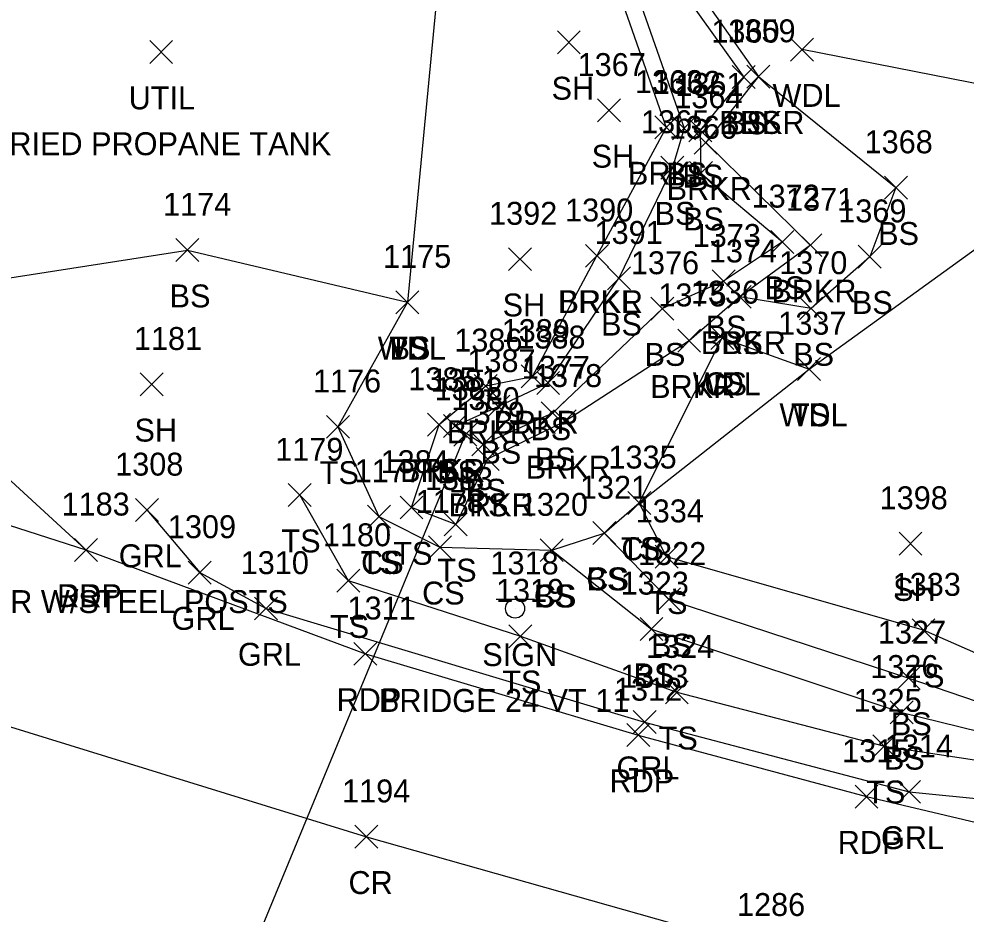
# Model space of a CAD drawing. Extents: x 1547013 to 1549434, y 267998 to 268739.
# Drawn here: x 1548542.6 to 1548625.3, y 268107.9 to 268186.1 of the extents above; entities that cross this region are included whole.
import ezdxf

# ---------------------------------------------------------------- set-up
doc = ezdxf.new("R2010")
doc.units = 0
for name, color, linetype in [('D_A', 7, 'Continuous'), ('D_I', 7, 'Continuous'), ('D_TIC', 7, 'Continuous'), ('DCP', 7, 'Continuous'), ('L_A', 7, 'Continuous'), ('L_I', 7, 'Continuous'), ('L_TIC', 7, 'Continuous'), ('LAWA', 7, 'Continuous'), ('LAWE', 7, 'Continuous'), ('LELB', 7, 'Continuous'), ('P_A', 7, 'Continuous'), ('P_I', 7, 'Continuous'), ('P_TIC', 7, 'Continuous'), ('PET', 7, 'Continuous'), ('PRC', 7, 'Continuous'), ('R_A', 7, 'Continuous'), ('R_C', 7, 'Continuous'), ('R_I', 7, 'Continuous'), ('R_TIC', 7, 'Continuous'), ('RDP', 7, 'Continuous'), ('RGR', 7, 'Continuous'), ('S_A', 7, 'Continuous'), ('S_C', 7, 'Continuous'), ('S_I', 7, 'Continuous'), ('SSGN', 7, 'Continuous'), ('U_A', 7, 'Continuous'), ('U_C', 7, 'Continuous'), ('UDEFAULT', 7, 'Continuous')]:
    doc.layers.add(name, color=color, linetype=linetype)

msp = doc.modelspace()

# ---------------------------------------------------------------- linework, layer by layer
at = {"layer": 'D_TIC'}
for points in [[(1548580.569, 268148.791), (1548582.569, 268150.791)], [(1548582.569, 268148.791), (1548580.569, 268150.791)]]:
    msp.add_lwpolyline(points, dxfattribs=at)
at = {"layer": 'DCP'}
msp.add_lwpolyline([(1548553.082, 268080.82), (1548581.569, 268149.791)], dxfattribs=at)
at = {"layer": 'L_TIC'}
for points in [[(1548589.597, 268183.027), (1548591.597, 268185.027)], [(1548591.597, 268183.027), (1548589.597, 268185.027)], [(1548609.953, 268182.401), (1548611.953, 268184.401)], [(1548611.953, 268182.401), (1548609.953, 268184.401)], [(1548604.859, 268180.006), (1548606.859, 268182.006)], [(1548606.859, 268180.006), (1548604.859, 268182.006)], [(1548606.135, 268180.039), (1548608.135, 268182.039)], [(1548608.135, 268180.039), (1548606.135, 268182.039)], [(1548606.135, 268180.039), (1548608.135, 268182.039)], [(1548608.135, 268180.039), (1548606.135, 268182.039)], [(1548593.098, 268177.092), (1548595.098, 268179.092)], [(1548595.098, 268177.092), (1548593.098, 268179.092)], [(1548598.102, 268175.604), (1548600.102, 268177.604)], [(1548600.102, 268175.604), (1548598.102, 268177.604)], [(1548599.647, 268175.537), (1548601.647, 268177.537)], [(1548601.647, 268175.537), (1548599.647, 268177.537)], [(1548601.065, 268175.361), (1548603.065, 268177.361)], [(1548603.065, 268175.361), (1548601.065, 268177.361)], [(1548601.54, 268174.278), (1548603.54, 268176.278)], [(1548603.54, 268174.278), (1548601.54, 268176.278)], [(1548598.633, 268172.103), (1548600.633, 268174.103)], [(1548600.633, 268172.103), (1548598.633, 268174.103)], [(1548601.121, 268171.618), (1548603.121, 268173.618)], [(1548603.121, 268171.618), (1548601.121, 268173.618)], [(1548618.144, 268170.348), (1548620.144, 268172.348)], [(1548620.144, 268170.348), (1548618.144, 268172.348)], [(1548608.234, 268165.605), (1548610.234, 268167.605)], [(1548610.234, 268165.605), (1548608.234, 268167.605)], [(1548556.31, 268164.896), (1548558.31, 268166.896)], [(1548558.31, 268164.896), (1548556.31, 268166.896)], [(1548610.675, 268165.326), (1548612.675, 268167.326)], [(1548612.675, 268165.326), (1548610.675, 268167.326)], [(1548585.328, 268164.108), (1548587.328, 268166.108)], [(1548587.328, 268164.108), (1548585.328, 268166.108)], [(1548592.044, 268164.396), (1548594.044, 268166.396)], [(1548594.044, 268164.396), (1548592.044, 268166.396)], [(1548592.044, 268164.396), (1548594.044, 268166.396)], [(1548594.044, 268164.396), (1548592.044, 268166.396)], [(1548615.854, 268164.32), (1548617.854, 268166.32)], [(1548617.854, 268164.32), (1548615.854, 268166.32)], [(1548593.964, 268162.437), (1548595.964, 268164.437)], [(1548595.964, 268162.437), (1548593.964, 268164.437)], [(1548593.964, 268162.437), (1548595.964, 268164.437)], [(1548595.964, 268162.437), (1548593.964, 268164.437)], [(1548603.096, 268162.172), (1548605.096, 268164.172)], [(1548605.096, 268162.172), (1548603.096, 268164.172)], [(1548604.509, 268160.821), (1548606.509, 268162.821)], [(1548606.509, 268160.821), (1548604.509, 268162.821)], [(1548604.509, 268160.821), (1548606.509, 268162.821)], [(1548606.509, 268160.821), (1548604.509, 268162.821)], [(1548575.504, 268160.346), (1548577.504, 268162.346)], [(1548577.504, 268160.346), (1548575.504, 268162.346)], [(1548575.504, 268160.346), (1548577.504, 268162.346)], [(1548577.504, 268160.346), (1548575.504, 268162.346)], [(1548575.504, 268160.346), (1548577.504, 268162.346)], [(1548577.504, 268160.346), (1548575.504, 268162.346)], [(1548597.76, 268159.793), (1548599.76, 268161.793)], [(1548599.76, 268159.793), (1548597.76, 268161.793)], [(1548610.73, 268159.799), (1548612.73, 268161.799)], [(1548612.73, 268159.799), (1548610.73, 268161.799)], [(1548600.099, 268156.985), (1548602.099, 268158.985)], [(1548602.099, 268156.985), (1548600.099, 268158.985)], [(1548602.989, 268157.225), (1548604.989, 268159.225)], [(1548604.989, 268157.225), (1548602.989, 268159.225)], [(1548602.989, 268157.225), (1548604.989, 268159.225)], [(1548604.989, 268157.225), (1548602.989, 268159.225)], [(1548610.56, 268154.512), (1548612.56, 268156.512)], [(1548612.56, 268154.512), (1548610.56, 268156.512)], [(1548610.56, 268154.512), (1548612.56, 268156.512)], [(1548612.56, 268154.512), (1548610.56, 268156.512)], [(1548586.429, 268153.87), (1548588.429, 268155.87)], [(1548588.429, 268153.87), (1548586.429, 268155.87)], [(1548587.793, 268153.304), (1548589.793, 268155.304)], [(1548589.793, 268153.304), (1548587.793, 268155.304)], [(1548553.197, 268153.181), (1548555.197, 268155.181)], [(1548555.197, 268153.181), (1548553.197, 268155.181)], [(1548582.343, 268153.042), (1548584.343, 268155.042)], [(1548584.343, 268153.042), (1548582.343, 268155.042)], [(1548583.434, 268151.245), (1548585.434, 268153.245)], [(1548585.434, 268151.245), (1548583.434, 268153.245)], [(1548588.179, 268150.662), (1548590.179, 268152.662)], [(1548590.179, 268150.662), (1548588.179, 268152.662)], [(1548589.244, 268149.946), (1548591.244, 268151.946)], [(1548591.244, 268149.946), (1548589.244, 268151.946)], [(1548569.443, 268149.472), (1548571.443, 268151.472)], [(1548571.443, 268149.472), (1548569.443, 268151.472)], [(1548578.272, 268149.661), (1548580.272, 268151.661)], [(1548580.272, 268149.661), (1548578.272, 268151.661)], [(1548578.272, 268149.661), (1548580.272, 268151.661)], [(1548580.272, 268149.661), (1548578.272, 268151.661)], [(1548579.655, 268149.536), (1548581.655, 268151.536)], [(1548581.655, 268149.536), (1548579.655, 268151.536)], [(1548582.124, 268147.933), (1548584.124, 268149.933)], [(1548584.124, 268147.933), (1548582.124, 268149.933)], [(1548582.506, 268146.655), (1548584.506, 268148.655)], [(1548584.506, 268146.655), (1548582.506, 268148.655)], [(1548582.506, 268146.655), (1548584.506, 268148.655)], [(1548584.506, 268146.655), (1548582.506, 268148.655)], [(1548566.105, 268143.51), (1548568.105, 268145.51)], [(1548568.105, 268143.51), (1548566.105, 268145.51)], [(1548595.744, 268142.829), (1548597.744, 268144.829)], [(1548597.744, 268142.829), (1548595.744, 268144.829)], [(1548595.744, 268142.829), (1548597.744, 268144.829)], [(1548597.744, 268142.829), (1548595.744, 268144.829)], [(1548573.025, 268141.632), (1548575.025, 268143.632)], [(1548575.025, 268141.632), (1548573.025, 268143.632)], [(1548573.025, 268141.632), (1548575.025, 268143.632)], [(1548575.025, 268141.632), (1548573.025, 268143.632)], [(1548575.861, 268142.428), (1548577.861, 268144.428)], [(1548577.861, 268142.428), (1548575.861, 268144.428)], [(1548579.72, 268140.956), (1548581.72, 268142.956)], [(1548581.72, 268140.956), (1548579.72, 268142.956)], [(1548592.686, 268140.194), (1548594.686, 268142.194)], [(1548594.686, 268140.194), (1548592.686, 268142.194)], [(1548592.686, 268140.194), (1548594.686, 268142.194)], [(1548594.686, 268140.194), (1548592.686, 268142.194)], [(1548619.408, 268139.276), (1548621.408, 268141.276)], [(1548621.408, 268139.276), (1548619.408, 268141.276)], [(1548578.349, 268138.961), (1548580.349, 268140.961)], [(1548580.349, 268138.961), (1548578.349, 268140.961)], [(1548588.098, 268138.705), (1548590.098, 268140.705)], [(1548590.098, 268138.705), (1548588.098, 268140.705)], [(1548588.098, 268138.705), (1548590.098, 268140.705)], [(1548590.098, 268138.705), (1548588.098, 268140.705)], [(1548598.121, 268138.132), (1548600.121, 268140.132)], [(1548600.121, 268138.132), (1548598.121, 268140.132)], [(1548570.343, 268136.045), (1548572.343, 268138.045)], [(1548572.343, 268136.045), (1548570.343, 268138.045)], [(1548598.329, 268134.41), (1548600.329, 268136.41)], [(1548600.329, 268134.41), (1548598.329, 268136.41)], [(1548596.809, 268131.823), (1548598.809, 268133.823)], [(1548598.809, 268131.823), (1548596.809, 268133.823)], [(1548620.549, 268131.719), (1548622.549, 268133.719)], [(1548622.549, 268131.719), (1548620.549, 268133.719)], [(1548585.37, 268131.193), (1548587.37, 268133.193)], [(1548587.37, 268131.193), (1548585.37, 268133.193)], [(1548619.257, 268127.544), (1548621.257, 268129.544)], [(1548621.257, 268127.544), (1548619.257, 268129.544)], [(1548599.022, 268126.304), (1548601.022, 268128.304)], [(1548601.022, 268126.304), (1548599.022, 268128.304)], [(1548618.648, 268124.545), (1548620.648, 268126.545)], [(1548620.648, 268124.545), (1548618.648, 268126.545)], [(1548617.136, 268121.596), (1548619.136, 268123.596)], [(1548619.136, 268121.596), (1548617.136, 268123.596)]]:
    msp.add_lwpolyline(points, dxfattribs=at)
at = {"layer": 'LAWA'}
for points in [[(1548576.365, 268223.8), (1548575.522, 268199.76), (1548579.378, 268191.112), (1548576.504, 268161.346)], [(1548603.989, 268158.225), (1548611.56, 268155.512), (1548628.675, 268167.856), (1548635.403, 268178.61), (1548610.953, 268183.401)]]:
    msp.add_lwpolyline(points, dxfattribs=at)
at = {"layer": 'LAWE'}
for points in [[(1548595.415, 268212.858), (1548593.341, 268193.065), (1548599.102, 268176.604), (1548593.044, 268165.396)], [(1548604.607, 268199.688), (1548599.756, 268191.551), (1548607.135, 268181.039), (1548602.54, 268175.278), (1548611.675, 268166.326), (1548605.509, 268161.821), (1548601.099, 268157.985), (1548590.244, 268150.946), (1548583.506, 268147.655)], [(1548579.272, 268150.661), (1548583.343, 268154.042), (1548587.429, 268154.87), (1548593.044, 268165.396)]]:
    msp.add_lwpolyline(points, dxfattribs=at)
at = {"layer": 'LELB'}
for points in [[(1548597.062, 268212.241), (1548594.748, 268193.422), (1548600.647, 268176.537), (1548599.633, 268173.103), (1548594.964, 268163.437)], [(1548641.103, 268197.228), (1548618.586, 268200.881), (1548604.348, 268203.165), (1548598.059, 268191.896), (1548605.859, 268181.006), (1548602.065, 268176.361), (1548602.121, 268172.618), (1548609.234, 268166.605), (1548604.096, 268163.172), (1548598.76, 268160.793), (1548589.179, 268151.662), (1548583.124, 268148.933), (1548580.655, 268150.536), (1548584.434, 268152.245), (1548588.793, 268154.304), (1548594.964, 268163.437)], [(1548607.135, 268181.039), (1548619.144, 268171.348), (1548616.854, 268165.32), (1548611.73, 268160.799), (1548605.509, 268161.821)], [(1548513.425, 268171.188), (1548524.997, 268163.116), (1548533.554, 268162.21), (1548557.31, 268165.896), (1548576.504, 268161.346)], [(1548576.504, 268161.346), (1548570.443, 268150.472), (1548574.025, 268142.632)], [(1548574.025, 268142.632), (1548579.349, 268139.961), (1548589.098, 268139.705), (1548593.686, 268141.194), (1548596.744, 268143.829), (1548603.989, 268158.225)], [(1548567.105, 268144.51), (1548571.343, 268137.045), (1548586.37, 268132.193), (1548600.022, 268127.304), (1548618.136, 268122.596), (1548638.08, 268119.574), (1548638.109, 268125.451), (1548621.549, 268132.719), (1548599.121, 268139.132), (1548596.744, 268143.829), (1548611.56, 268155.512)], [(1548583.506, 268147.655), (1548580.72, 268141.956), (1548576.861, 268143.428), (1548579.272, 268150.661)], [(1548593.686, 268141.194), (1548599.329, 268135.41), (1548620.257, 268128.544), (1548636.788, 268122.874), (1548636.589, 268121.375)], [(1548589.098, 268139.705), (1548597.809, 268132.823), (1548619.648, 268125.545), (1548636.589, 268121.375)]]:
    msp.add_lwpolyline(points, dxfattribs=at)
at = {"layer": 'P_TIC'}
for points in [[(1548547.446, 268138.726), (1548549.446, 268140.726)], [(1548549.446, 268138.726), (1548547.446, 268140.726)], [(1548571.84, 268129.652), (1548573.84, 268131.652)], [(1548573.84, 268129.652), (1548571.84, 268131.652)], [(1548595.653, 268122.565), (1548597.653, 268124.565)], [(1548597.653, 268122.565), (1548595.653, 268124.565)], [(1548615.573, 268117.195), (1548617.573, 268119.195)], [(1548617.573, 268117.195), (1548615.573, 268119.195)], [(1548571.932, 268113.689), (1548573.932, 268115.689)], [(1548573.932, 268113.689), (1548571.932, 268115.689)]]:
    msp.add_lwpolyline(points, dxfattribs=at)
at = {"layer": 'PET'}
msp.add_lwpolyline([(1548291.291, 268251.793), (1548331.751, 268232.06), (1548365.572, 268215.99), (1548397.036, 268199.918), (1548430.532, 268185.01), (1548469.559, 268167.88), (1548505.567, 268153.53), (1548548.446, 268139.726), (1548572.84, 268130.652), (1548596.653, 268123.565), (1548616.573, 268118.195), (1548655.338, 268109.044), (1548680.933, 268103.123), (1548700.801, 268099.763), (1548753.548, 268092.312), (1548788.113, 268088.532), (1548842.075, 268084.262), (1548868.979, 268083.237)], dxfattribs=at)
at = {"layer": 'PRC'}
msp.add_lwpolyline([(1548285.227, 268237.15), (1548330.43, 268214.749), (1548376.37, 268192.576), (1548426.535, 268169.593), (1548464.29, 268153.498), (1548497.35, 268140.085), (1548534.695, 268126.495), (1548572.932, 268114.689), (1548608.018, 268104.772), (1548637.809, 268097.375), (1548663.07, 268091.687), (1548686.377, 268086.96), (1548723.692, 268081.048), (1548751.899, 268076.9), (1548786.742, 268073.357), (1548818.759, 268070.537), (1548866.796, 268068.078)], dxfattribs=at)
at = {"layer": 'R_TIC'}
for points in [[(1548552.774, 268142.213), (1548554.774, 268144.213)], [(1548554.774, 268142.213), (1548552.774, 268144.213)], [(1548547.446, 268138.726), (1548549.446, 268140.726)], [(1548549.446, 268138.726), (1548547.446, 268140.726)], [(1548557.382, 268136.75), (1548559.382, 268138.75)], [(1548559.382, 268136.75), (1548557.382, 268138.75)], [(1548563.172, 268133.614), (1548565.172, 268135.614)], [(1548565.172, 268133.614), (1548563.172, 268135.614)], [(1548596.208, 268123.696), (1548598.208, 268125.696)], [(1548598.208, 268123.696), (1548596.208, 268125.696)], [(1548619.291, 268117.608), (1548621.291, 268119.608)], [(1548621.291, 268117.608), (1548619.291, 268119.608)]]:
    msp.add_lwpolyline(points, dxfattribs=at)
at = {"layer": 'RDP'}
msp.add_lwpolyline([(1548480.171, 268203.984), (1548501.427, 268182.211), (1548512.877, 268169.309), (1548535.027, 268152.048), (1548548.446, 268139.726)], dxfattribs=at)
at = {"layer": 'RGR'}
msp.add_lwpolyline([(1548553.774, 268143.213), (1548558.382, 268137.75), (1548564.172, 268134.614), (1548597.208, 268124.696), (1548620.291, 268118.608), (1548649.201, 268115.719)], dxfattribs=at)
at = {"layer": 'SSGN'}
for p, q in [((1548584.254, 268135.438), (1548587.588, 268135.438)), ((1548585.901, 268134.605), (1548585.901, 268134.605))]:
    msp.add_line(p, q, dxfattribs=at)
msp.add_circle((1548585.901, 268134.605), 0.833, dxfattribs=at)
at = {"layer": 'UDEFAULT'}
for points in [[(1548554.013, 268182.182), (1548556.013, 268184.182)], [(1548556.013, 268182.182), (1548554.013, 268184.182)]]:
    msp.add_lwpolyline(points, dxfattribs=at)

# ---------------------------------------------------------------- texts
at = {"layer": 'D_A'}
msp.add_text('P', height=2, dxfattribs=at).set_placement((1548580.947, 268144.791))
at = {"layer": 'D_I'}
msp.add_text('1382', height=2, dxfattribs=at).set_placement((1548578.876, 268152.791))
at = {"layer": 'L_A'}
for s, p in [('SH', (1548589.086, 268179.027)), ('WDL', (1548608.37, 268178.401)), ('BRKR', (1548603.726, 268176.039)), ('BS', (1548604.3, 268176.006)), ('BS', (1548605.576, 268176.039)), ('SH', (1548592.586, 268173.092)), ('BRKL', (1548595.748, 268171.604)), ('BS', (1548599.088, 268171.537)), ('BS', (1548600.506, 268171.361)), ('BRKR', (1548599.13, 268170.278)), ('BS', (1548598.074, 268168.103)), ('BS', (1548600.562, 268167.618)), ('BS', (1548617.585, 268166.348)), ('BS', (1548607.675, 268161.605)), ('BS', (1548555.751, 268160.896)), ('BRKR', (1548608.266, 268161.326)), ('SH', (1548584.816, 268160.108)), ('BRKR', (1548589.634, 268160.396)), ('BRKL', (1548589.689, 268160.396)), ('BS', (1548615.295, 268160.32)), ('BS', (1548593.405, 268158.437)), ('BS', (1548593.405, 268158.437)), ('BS', (1548602.537, 268158.172)), ('BRKR', (1548602.1, 268156.821)), ('BS', (1548603.95, 268156.821)), ('WDL', (1548573.922, 268156.346)), ('TS', (1548574.914, 268156.346)), ('BS', (1548574.945, 268156.346)), ('BS', (1548597.201, 268155.793)), ('BS', (1548610.171, 268155.799)), ('WDL', (1548601.406, 268153.225)), ('CS', (1548602.43, 268153.225)), ('BRKR', (1548597.69, 268152.985)), ('WDL', (1548608.977, 268150.512)), ('TS', (1548609.969, 268150.512)), ('SH', (1548552.685, 268149.181)), ('BRKR', (1548584.019, 268149.87)), ('BS', (1548587.234, 268149.304)), ('BRKR', (1548579.934, 268149.042)), ('BS', (1548582.875, 268147.245)), ('BS', (1548587.62, 268146.662)), ('BRKR', (1548586.835, 268145.946)), ('TS', (1548568.853, 268145.472)), ('BRKR', (1548575.863, 268145.661)), ('TS', (1548577.682, 268145.661)), ('BS', (1548579.096, 268145.536)), ('BS', (1548581.565, 268143.933)), ('BRKR', (1548580.096, 268142.655)), ('TS', (1548581.915, 268142.655)), ('TS', (1548565.514, 268139.51)), ('TS', (1548575.271, 268138.428)), ('TS', (1548595.154, 268138.829)), ('CS', (1548595.185, 268138.829)), ('TS', (1548572.434, 268137.632)), ('CS', (1548572.466, 268137.632)), ('TS', (1548579.13, 268136.956)), ('CS', (1548592.127, 268136.194)), ('BS', (1548592.127, 268136.194)), ('SH', (1548618.896, 268135.276)), ('CS', (1548577.79, 268134.961)), ('CS', (1548587.539, 268134.705)), ('BS', (1548587.539, 268134.705)), ('TS', (1548597.531, 268134.132)), ('TS', (1548569.752, 268132.045)), ('BS', (1548597.77, 268130.41)), ('BS', (1548596.25, 268127.823)), ('TS', (1548619.959, 268127.719)), ('TS', (1548584.78, 268127.193)), ('BS', (1548618.697, 268123.544)), ('TS', (1548598.431, 268122.304)), ('BS', (1548618.089, 268120.545)), ('TS', (1548616.545, 268117.596))]:
    msp.add_text(s, height=2, dxfattribs=at).set_placement(p)
at = {"layer": 'L_I'}
for s, p in [('1360', (1548603.032, 268184.006)), ('1359', (1548604.434, 268184.039)), ('1359', (1548604.434, 268184.039)), ('1367', (1548591.358, 268181.092)), ('1363', (1548596.362, 268179.604)), ('1362', (1548597.907, 268179.537)), ('1361', (1548599.892, 268179.361)), ('1364', (1548599.8, 268178.278)), ('1365', (1548596.893, 268176.103)), ('1366', (1548599.326, 268175.618)), ('1368', (1548616.404, 268174.348)), ('1372', (1548606.541, 268169.605)), ('1371', (1548609.549, 268169.326)), ('1174', (1548555.184, 268168.896)), ('1392', (1548583.635, 268168.108)), ('1390', (1548590.264, 268168.396)), ('1390', (1548590.264, 268168.396)), ('1369', (1548614.106, 268168.32)), ('1391', (1548592.838, 268166.437)), ('1391', (1548592.838, 268166.437)), ('1373', (1548601.403, 268166.172)), ('1374', (1548602.816, 268164.821)), ('1374', (1548602.816, 268164.821)), ('1175', (1548574.379, 268164.346)), ('1175', (1548574.379, 268164.346)), ('1175', (1548574.379, 268164.346)), ('1376', (1548596.012, 268163.793)), ('1370', (1548608.951, 268163.799)), ('1375', (1548598.407, 268160.985)), ('1336', (1548601.241, 268161.225)), ('1336', (1548601.241, 268161.225)), ('1337', (1548608.867, 268158.512)), ('1337', (1548608.867, 268158.512)), ('1389', (1548584.728, 268157.87)), ('1181', (1548552.638, 268157.181)), ('1386', (1548580.595, 268157.042)), ('1388', (1548586.1, 268157.304)), ('1387', (1548581.741, 268155.245)), ('1377', (1548586.486, 268154.662)), ('1176', (1548568.263, 268153.472)), ('1385', (1548576.58, 268153.661)), ('1385', (1548576.58, 268153.661)), ('1381', (1548578.529, 268153.536)), ('1378', (1548587.552, 268153.946)), ('1380', (1548580.345, 268151.933)), ('1379', (1548580.805, 268150.655)), ('1379', (1548580.805, 268150.655)), ('1179', (1548564.971, 268147.51)), ('1335', (1548594.052, 268146.829)), ('1335', (1548594.052, 268146.829)), ('1384', (1548574.169, 268146.428)), ('1177', (1548571.899, 268145.632)), ('1177', (1548571.899, 268145.632)), ('1383', (1548578.028, 268144.956)), ('1321', (1548591.561, 268144.194)), ('1321', (1548591.561, 268144.194)), ('1398', (1548617.715, 268143.276)), ('1178', (1548577.223, 268142.961)), ('1320', (1548586.318, 268142.705)), ('1320', (1548586.318, 268142.705)), ('1334', (1548596.429, 268142.132)), ('1180', (1548569.13, 268140.045)), ('1322', (1548596.637, 268138.41)), ('1323', (1548595.117, 268135.823)), ('1319', (1548584.237, 268135.193)), ('1333', (1548618.856, 268135.719)), ('1327', (1548617.564, 268131.544)), ('1324', (1548597.329, 268130.304)), ('1326', (1548616.901, 268128.545)), ('1325', (1548615.443, 268125.596))]:
    msp.add_text(s, height=2, dxfattribs=at).set_placement(p)
at = {"layer": 'P_A'}
for s, p in [('RDP', (1548545.934, 268134.726)), ('RDP', (1548570.328, 268125.652)), ('RDP', (1548594.141, 268118.565)), ('RDP', (1548614.061, 268113.195)), ('CR', (1548571.365, 268109.689))]:
    msp.add_text(s, height=2, dxfattribs=at).set_placement(p)
at = {"layer": 'P_I'}
for s, p in [('1183', (1548546.32, 268142.726)), ('1311', (1548571.281, 268133.652)), ('1312', (1548594.527, 268126.565)), ('1315', (1548614.447, 268121.195)), ('1194', (1548570.807, 268117.689)), ('1286', (1548605.271, 268107.772))]:
    msp.add_text(s, height=2, dxfattribs=at).set_placement(p)
at = {"layer": 'R_A'}
for s, p in [('GRL', (1548551.317, 268138.213)), ('DRP', (1548545.934, 268134.726)), ('GRL', (1548555.925, 268132.75)), ('GRL', (1548561.716, 268129.614)), ('GRL', (1548594.751, 268119.696)), ('GRL', (1548617.835, 268113.608))]:
    msp.add_text(s, height=2, dxfattribs=at).set_placement(p)
at = {"layer": 'R_C'}
msp.add_text('SGR W/STEEL POSTS', height=2, dxfattribs=at).set_placement((1548537.979, 268134.213))
at = {"layer": 'R_I'}
for s, p in [('1308', (1548551.002, 268146.213)), ('1183', (1548546.32, 268142.726)), ('1309', (1548555.602, 268140.75)), ('1310', (1548561.96, 268137.614)), ('1313', (1548595.082, 268127.696)), ('1314', (1548618.166, 268121.608))]:
    msp.add_text(s, height=2, dxfattribs=at).set_placement(p)
at = {"layer": 'S_A'}
msp.add_text('SIGN', height=2, dxfattribs=at).set_placement((1548583.039, 268129.585))
at = {"layer": 'S_C'}
msp.add_text('BRIDGE 24 VT 11', height=2, dxfattribs=at).set_placement((1548574.024, 268125.585))
at = {"layer": 'S_I'}
msp.add_text('1318', height=2, dxfattribs=at).set_placement((1548583.756, 268137.585))
at = {"layer": 'U_A'}
msp.add_text('UTIL', height=2, dxfattribs=at).set_placement((1548552.179, 268178.182))
at = {"layer": 'U_C'}
msp.add_text('BURIED PROPANE TANK', height=2, dxfattribs=at).set_placement((1548538.053, 268174.182))

doc.saveas('drawing.dxf')
